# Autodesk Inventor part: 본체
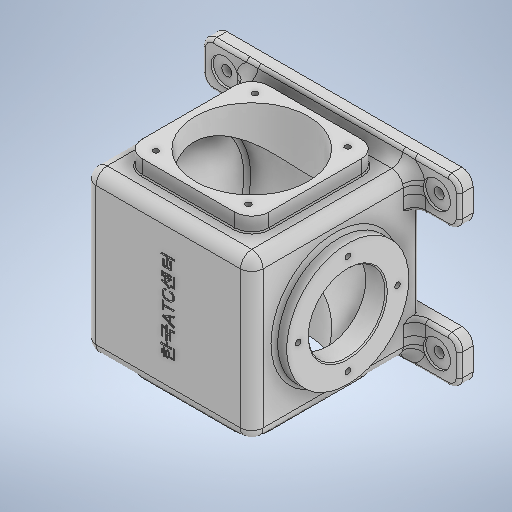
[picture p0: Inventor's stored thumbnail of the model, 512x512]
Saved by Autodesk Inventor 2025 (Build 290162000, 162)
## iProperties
Created: 2026-01
Part Number: 본체
Material: 일반
Document SubType Name: Modeling
Designer: KDI
Density: 1 g/cm^3
Appearance: 기본값
Author: KDI
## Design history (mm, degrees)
sketch "스케치2"
  geometry: L1 (114, 81)-(-114, 81); L2 (-114, -81)-(114, -81); L3 (114, 81)-(-114, -81); L4 (-114, 81)-(114, -81); L5 (-114, 41)-(114, 41); L6 (0, 0)-(14.996, 0); L7 (-114, -41)-(114, -41); L8 (-114, 81)-(-114, 41); L9 (-114, -41)-(-114, -81); L10 (114, -81)-(114, -41); L11 (114, 41)-(114, 81)
  constraints: 22 end point, 5 parallel, 4 perpendicular, 2 horizontal, 2 midpoint, 2 symmetric about line
  dimensions: "d0" = 228 distance of L2.end L2.start; "d1" = 162 distance of L2.start L1.end
extrude "돌출1" new body sketch "스케치2" distance "d3" = 12; taper "d4" = 0 deg
node "작업 평면1"
sketch "스케치3"
  geometry: L1 (-74, 71)-(74, 71); L2 (74, 71)-(74, -71); L3 (74, -71)-(-74, -71); L4 (-74, -71)-(-74, 71); L5 (-74, 71)-(74, -71); L6 (74, 71)-(-74, -71); 1 further point
  constraints: 12 end point, 2 midpoint, 2 parallel, 1 horizontal, 1 perpendicular
  dimensions: "d6" = 148 distance of L2.end L3.end; "d7" = 142 distance of L1.end L2.end
extrude "돌출2" join sketch "스케치3" distance "d8" = 148; taper "d9" = 0 deg
fillet "모깎기1" dims "d10" = 10
sketch "스케치7"
  geometry: 5 further points
hole "구멍2" sketch "스케치7" at (-94, -61), (-94, 61), (94, 61), (94, -61) diameter "d38" = 9; stored, may be unused: countersink angle "d42" = 82 deg, drill point angle "d44" = 118 deg; dims "d39" = 12, "d40" = 24, "d41" = 2, "d43" = 15
sketch "스케치8"
  geometry: L1 (23, -8)-(105, -8); L2 (120, -23)-(120, -105); L3 (105, -120)-(23, -120); L4 (8, -105)-(8, -23); L5 (8, -8)-(120, -120); L6 (120, -8)-(8, -120); A1 r 15 centre (23, -23) between (23, -8) and (8, -23); A2 r 15 centre (23, -105) between (8, -105) and (23, -120); A3 r 15 centre (105, -105) between (105, -120) and (120, -105); A4 r 15 centre (105, -23) between (120, -23) and (105, -8); 1 further point
  constraints: 12 end point, 8 point on circle, 8 point on line, 8 tangent, 4 centre point, 3 equal radius, 2 parallel, 1 horizontal, 1 perpendicular
  dimensions: "d46" = 112 distance of L5.end L6.end; "d47" = 112 distance of L6.start L5.end; "d48" = 15 radius of A1 (derived)
extrude "돌출5" join sketch "스케치8" distance "d49" = 13; taper "d50" = 0 deg
sketch "스케치9"
  geometry: L1 (128, -134)-(128, 0) reference; L2 (0, -134)-(128, -134) reference; L3 (0, 0)-(0, -134) reference; L4 (128, 0)-(0, 0) reference; C1 r 50 at (64, -64); 1 further point
  constraints: 1 centre point
  dimensions: "d52" = 100 diameter of C1
extrude "돌출6" cut sketch "스케치9" distance "d53" = 13; taper "d54" = 0 deg
sketch "스케치10"
  geometry: 5 further points
hole "구멍3" sketch "스케치10" at (23, -20), (105, -20), (105, -108), (23, -108) diameter "d58" = 4.917; stored, may be unused: countersink angle "d62" = 90 deg, drill point angle "d64" = 118 deg; dims "d59" = 12, "d60" = 3.6, "d61" = 2, "d63" = 14
chamfer "모따기2" distance "d65" = 1; stored, may be unused: second distance "d66" = 2, angle "d67" = 45 deg
chamfer "모따기3" distance "d68" = 1; stored, may be unused: second distance "d69" = 2, angle "d70" = 45 deg
sketch "스케치11"
  geometry: C1 r 50 at (0, 0); 1 further point
  constraints: 1 centre point
extrude "돌출7" cut sketch "스케치11" extent not by distance; stored distance "d71" = 0; taper "d72" = 0 deg
fillet "모깎기2" dims "d73" = 10
sketch "스케치12"
  geometry: C1 r 54 at (-74, 41); 1 further point
  constraints: 1 centre point
  dimensions: "d76" = 108 diameter of C1
extrude "돌출8" join sketch "스케치12" distance "d77" = 11; taper "d78" = 0 deg
sketch "스케치13"
  geometry: C1 r 34 at (0, 0); 1 further point
  constraints: 1 centre point
  dimensions: "d79" = 68 diameter of C1
extrude "돌출9" cut sketch "스케치13" distance "d80" = 87.5; taper "d81" = 0 deg
sketch "스케치14"
  geometry: 2 further points
hole "구멍4" sketch "스케치14" at (-44, 0) diameter "d83" = 4.917; stored, may be unused: countersink angle "d87" = 90 deg, drill point angle "d89" = 118 deg; dims "d84" = 12, "d85" = 4, "d86" = 2, "d88" = 14
fillet "모깎기4" dims "d93" = 3
sketch "스케치15"
  geometry: 2 further points
  constraints: 2 coincident, 1 other
feature "엠보싱1" sketch "스케치15" dims "d94" = 0.5, "d95" = 0
fillet "모깎기5" dims "d96" = 3
fillet "모깎기6" dims "d97" = 10
fillet "모깎기7" dims "d98" = 3
chamfer "모따기4" distance "d99" = 1; stored, may be unused: second distance "d100" = 2, angle "d101" = 45 deg
sketch "스케치16"
  geometry: L1 (159.6, 8)-(-159.6, 8) reference; L2 (74, 22)-(74, 146) reference; L3 (64, 156)-(-64, 156) reference; L4 (-74, 146)-(-74, 22) reference; L5 (64, 149)-(-64, 149); L6 (67, 84)-(67, 146); L7 (-67, 146)-(-67, 84); L8 (-67, 84)-(74, 84); A1 r 3 centre (64, 146) between (67, 146) and (64, 149); A2 r 3 centre (-64, 146) between (-64, 149) and (-67, 146); 1 further point
  constraints: 8 end point, 4 point on circle, 4 tangent, 3 parallel, 2 centre point, 1 midpoint, 1 point on line
  dimensions: "d102" = 7 distance between parallel lines of L3 L5; "d103" = 7 distance between parallel lines of L2 L6; "d104" = 7 distance between parallel lines of L4 L7
revolve "회전1" sketch "스케치16" stored, may be unused: angle "d106" = 90 deg
node "솔리드1"
mirror "미러2"
mirror "미러3"
pattern_circular "원형 패턴1" dims angle "d91" = 360 deg
node "투영된 루프1"
feature "A9D066F2-1C7D-4E18-AEED-F7BC21143FA4" dims "d38" = 9, "d39" = 12, "d40" = 24, "d41" = 2, "d42" = 82 deg, "d43" = 15, "d44" = 118 deg
other parameters: "d5" = -8
